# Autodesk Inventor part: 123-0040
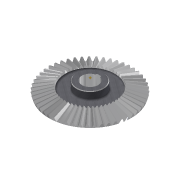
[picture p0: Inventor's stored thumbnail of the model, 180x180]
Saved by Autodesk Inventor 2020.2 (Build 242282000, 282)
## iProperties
+MSCProtocol1+ProtocolID: P00060228092509906
+MSCProtocol2+Protocol: P00060228092509906<@PID>[Version]<@EL>Version=2.2<@EL>[Main]<@EL>VarLists=A,B,C,D,E,F,K<@EL>PartKey=Gears<@EL>Standard=DIN<@EL>View=MODELB<@EL>DataFile=SPIDATA|
Manager: www.cadconsulting.pl
Company: Fabian Stasiak CAD Consulting
Shininess: 20.0
Length Units: 11269
Angle Units: 11279
Time Units: 11290
Mass Units: 11283
Length Display Precision: 3
Angle Display Precision: 2
Created: 2001-01
Part Number: 123-0040
Material: Stal 60
Document SubType Name: Modeling
Description: Koło zęb. stożkowe z=51
Project: Przekładnia X51
Designer: F.Stasiak
Mass: 1037.27 g
Surface Area: 571.297 cm^2
Volume: 132.136 cm^3
Density: 7.85 g/cm^3
Appearance: Chrom
Density: 7.86
Volumn: 5.864026952018771
Area: 31.42094824814569
PropertySet Name: Model Information
Control State: 0
Master: False
Checked Out: False
TAB_mte: 3
TAB_z1: 15
TAB_z2: 51
TAB_betam: 20
TAB_x: 0.1632
TAB_xt: 0
TAB_delta1: 16.3895
TAB_delta2: 73.6105
TAB_IT: 6e26
TAB_fpt1: ±0.01
TAB_fpt2: ±0.011
TAB_tfa: 0
TAB_sk1: 4.305
TAB_sk2: 3.699
TAB_ECs1: -0.03
TAB_ECd1: -0.08
TAB_ECs2: -0.04
TAB_ECd2: -0.1
TAB_hk1: 2.706
TAB_hk2: 1.837
TAB_omega: 90
TAB_de1: 45
TAB_de2: 153
TAB_le: 79.74
TAB_deltaf1: 14.1558
TAB_deltaf2: 70.6745
TAB_alfat: 20
Author: F.Stasiak
Subject: Zbiór ćwiczeń. Autodesk Inventor 2020. Kurs podstawowy
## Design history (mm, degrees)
node "Bryła1"
node "Korpusy bryłowe"
node "Korpusy powierzchniowe"
revolve "Base Body" stored, may be unused: angle "d10" = 360 deg
node "Tooth Plane"
workpoint "Work Point"
sketch "Sketch2"
  geometry: L1 (4.216, 3.832)-(-4.216, 3.832); L2 (0, -6.728)-(4.216, 3.832); L3 (-4.216, 3.832)-(0, -6.728); L4 (0, 2.5)-(0, -3) reference; L5 (0, 2.5)-(0, -3) reference; L6 (0, 2.5)-(0, -3) reference; L7 (0, -73.314)-(0, 27.014) reference; L8 (0, -73.314)-(0, 27.014) reference; L9 (92.65, -15.24)-(-123.534, -15.24) reference; A1 r 6.122 centre (0, -0.607) between (-4.216, 3.832) and (0, -6.728); 1 further point; 1 other entity
  constraints: 6 end point, 3 point on circle, 2 point on line, 1 centre point, 1 horizontal, 1 vertical alignment, 1 other
  dimensions: "d42" = 43.5294 deg angle of L3 L2 (= msp_a2); "d43" = 10.56 distance from line of L2.start L1 (= 1.6 x msp_he); "d54" = 12.54559 distance of L2.start point (0, -19.274) (= msp_y)
extrude "Tooth" cut sketch "Sketch2" distance "d18" = 32.436 (= 1.02 x prf_b); taper "d19" = -1.88111 deg (= msp_a1)
pattern_circular "Tooth Pattern" dims angle "d22" = 360 deg
revolve "Fix Body" stored, may be unused: angle "d23" = 360 deg
sketch "Sketch7"
  geometry: L1 (-28.8, 0)-(38.4, 0) reference; L2 (0, -28.8)-(0, 38.4) reference; 2 further points
  constraints: 1 coincident
hole "Hole" sketch "Sketch7" diameter "d47" = 37.673 (= hole); stored, may be unused: countersink angle "d51" = 60 deg, drill point angle "d53" = 118 deg; dims "d48" = 6, "d49" = 4, "d50" = 2, "d52" = 8
node "Gear Axis"
node "Mesh Plane"
node "Intersection"
sketch "Szkic8"
  geometry: C1 r 25 at (0, 0); A1 r 45.298 centre (0, 0) between (32.114, -31.947) and (32.921, -31.115) reference; A2 r 45.298 centre (0, 0) between (32.921, -31.115) and (35.797, -27.759) reference; A3 r 45.298 centre (0, 0) between (35.797, -27.759) and (36.495, -26.833) reference; A4 r 45.298 centre (0, 0) between (36.495, -26.833) and (38.936, -23.149) reference; A5 r 45.298 centre (0, 0) between (38.936, -23.149) and (39.516, -22.145) reference; A6 r 45.298 centre (0, 0) between (39.516, -22.145) and (41.486, -18.189) reference; A7 r 45.298 centre (0, 0) between (41.486, -18.189) and (41.938, -17.121) reference; A8 r 45.298 centre (0, 0) between (41.938, -17.121) and (43.407, -12.953) reference; A9 r 45.298 centre (0, 0) between (43.407, -12.953) and (43.724, -11.838) reference; A10 r 45.298 centre (0, 0) between (43.724, -11.838) and (44.67, -7.521) reference; A11 r 45.298 centre (0, 0) between (44.67, -7.521) and (44.847, -6.375) reference; A12 r 45.298 centre (0, 0) between (44.847, -6.375) and (45.255, -1.974) reference; A13 r 45.298 centre (0, 0) between (45.255, -1.974) and (45.291, -0.815) reference; A14 r 45.298 centre (0, 0) between (45.291, -0.815) and (45.155, 3.602) reference; A15 r 45.298 centre (0, 0) between (45.155, 3.602) and (45.048, 4.756) reference; A16 r 45.298 centre (0, 0) between (45.048, 4.756) and (44.37, 9.124) reference; A17 r 45.298 centre (0, 0) between (44.37, 9.124) and (44.122, 10.256) reference; A18 r 45.298 centre (0, 0) between (44.122, 10.256) and (42.912, 14.507) reference; A19 r 45.298 centre (0, 0) between (42.912, 14.507) and (42.527, 15.601) reference; A20 r 45.298 centre (0, 0) between (42.527, 15.601) and (40.804, 19.671) reference; A21 r 45.298 centre (0, 0) between (40.804, 19.671) and (40.288, 20.708) reference; A22 r 45.298 centre (0, 0) between (40.288, 20.708) and (38.078, 24.536) reference; A23 r 45.298 centre (0, 0) between (38.078, 24.536) and (37.437, 25.502) reference; A24 r 45.298 centre (0, 0) between (37.437, 25.502) and (34.774, 29.029) reference; A25 r 45.298 centre (0, 0) between (34.774, 29.029) and (34.02, 29.91) reference; A26 r 45.298 centre (0, 0) between (34.02, 29.91) and (30.943, 33.083) reference; A27 r 45.298 centre (0, 0) between (30.943, 33.083) and (30.086, 33.864) reference; A28 r 45.298 centre (0, 0) between (30.086, 33.864) and (26.643, 36.634) reference; A29 r 45.298 centre (0, 0) between (26.643, 36.634) and (25.697, 37.304) reference; A30 r 45.298 centre (0, 0) between (25.697, 37.304) and (21.939, 39.631) reference; A31 r 45.298 centre (0, 0) between (21.939, 39.631) and (20.918, 40.179) reference; A32 r 45.298 centre (0, 0) between (20.918, 40.179) and (16.903, 42.027) reference; A33 r 45.298 centre (0, 0) between (16.903, 42.027) and (15.822, 42.445) reference; A34 r 45.298 centre (0, 0) between (15.822, 42.445) and (11.61, 43.785) reference; A35 r 45.298 centre (0, 0) between (11.61, 43.785) and (10.486, 44.068) reference; A36 r 45.298 centre (0, 0) between (10.486, 44.068) and (6.141, 44.88) reference; A37 r 45.298 centre (0, 0) between (6.141, 44.88) and (4.991, 45.023) reference; A38 r 45.298 centre (0, 0) between (4.991, 45.023) and (0.58, 45.295) reference; A39 r 45.298 centre (0, 0) between (0.58, 45.295) and (-0.58, 45.295) reference; A40 r 45.298 centre (0, 0) between (-0.58, 45.295) and (-4.991, 45.023) reference; A41 r 45.298 centre (0, 0) between (-4.991, 45.023) and (-6.141, 44.88) reference; A42 r 45.298 centre (0, 0) between (-6.141, 44.88) and (-10.486, 44.068) reference; A43 r 45.298 centre (0, 0) between (-10.486, 44.068) and (-11.61, 43.785) reference; A44 r 45.298 centre (0, 0) between (-11.61, 43.785) and (-15.822, 42.445) reference; A45 r 45.298 centre (0, 0) between (-15.822, 42.445) and (-16.903, 42.027) reference; A46 r 45.298 centre (0, 0) between (-16.903, 42.027) and (-20.918, 40.179) reference; A47 r 45.298 centre (0, 0) between (-20.918, 40.179) and (-21.939, 39.631) reference; A48 r 45.298 centre (0, 0) between (-21.939, 39.631) and (-25.697, 37.304) reference; A49 r 45.298 centre (0, 0) between (-25.697, 37.304) and (-26.643, 36.634) reference; A50 r 45.298 centre (0, 0) between (-26.643, 36.634) and (-30.086, 33.864) reference; A51 r 45.298 centre (0, 0) between (-30.086, 33.864) and (-30.943, 33.083) reference; A52 r 45.298 centre (0, 0) between (-30.943, 33.083) and (-34.02, 29.91) reference; A53 r 45.298 centre (0, 0) between (-34.02, 29.91) and (-34.774, 29.029) reference; A54 r 45.298 centre (0, 0) between (-34.774, 29.029) and (-37.437, 25.502) reference; A55 r 45.298 centre (0, 0) between (-37.437, 25.502) and (-38.078, 24.536) reference; A56 r 45.298 centre (0, 0) between (-38.078, 24.536) and (-40.288, 20.708) reference; A57 r 45.298 centre (0, 0) between (-40.288, 20.708) and (-40.804, 19.671) reference; A58 r 45.298 centre (0, 0) between (-40.804, 19.671) and (-42.527, 15.601) reference; A59 r 45.298 centre (0, 0) between (-42.527, 15.601) and (-42.912, 14.507) reference; A60 r 45.298 centre (0, 0) between (-42.912, 14.507) and (-44.122, 10.256) reference; A61 r 45.298 centre (0, 0) between (-44.122, 10.256) and (-44.37, 9.124) reference; A62 r 45.298 centre (0, 0) between (-44.37, 9.124) and (-45.048, 4.756) reference; A63 r 45.298 centre (0, 0) between (-45.048, 4.756) and (-45.155, 3.602) reference; A64 r 45.298 centre (0, 0) between (-45.155, 3.602) and (-45.291, -0.815) reference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
  constraints: 1 centre point, 1 coincident
  dimensions: "d69" = 50 diameter of C1
extrude "Wyciągnięcie proste2" join sketch "Szkic8" distance "d70" = 12; taper "d71" = 0 deg
sketch "Szkic9"
  geometry: C1 r 25 at (0, 0); A1 r 75.346 centre (0, 0) between (65.772, -36.758) and (68.969, -30.335) reference; A2 r 75.346 centre (0, 0) between (68.969, -30.335) and (69.79, -28.397) reference; A3 r 75.346 centre (0, 0) between (69.79, -28.397) and (72.175, -21.63) reference; A4 r 75.346 centre (0, 0) between (72.175, -21.63) and (72.751, -19.605) reference; A5 r 75.346 centre (0, 0) between (72.751, -19.605) and (74.286, -12.597) reference; A6 r 75.346 centre (0, 0) between (74.286, -12.597) and (74.609, -10.516) reference; A7 r 75.346 centre (0, 0) between (74.609, -10.516) and (75.27, -3.372) reference; A8 r 75.346 centre (0, 0) between (75.27, -3.372) and (75.335, -1.268) reference; A9 r 75.346 centre (0, 0) between (75.335, -1.268) and (75.114, 5.903) reference; A10 r 75.346 centre (0, 0) between (75.114, 5.903) and (74.92, 8) reference; A11 r 75.346 centre (0, 0) between (74.92, 8) and (73.82, 15.089) reference; A12 r 75.346 centre (0, 0) between (73.82, 15.089) and (73.369, 17.146) reference; A13 r 75.346 centre (0, 0) between (73.369, 17.146) and (71.406, 24.046) reference; A14 r 75.346 centre (0, 0) between (71.406, 24.046) and (70.706, 26.032) reference; A15 r 75.346 centre (0, 0) between (70.706, 26.032) and (67.91, 32.639) reference; A16 r 75.346 centre (0, 0) between (67.91, 32.639) and (66.971, 34.524) reference; A17 r 75.346 centre (0, 0) between (66.971, 34.524) and (63.384, 40.737) reference; A18 r 75.346 centre (0, 0) between (63.384, 40.737) and (62.221, 42.492) reference; A19 r 75.346 centre (0, 0) between (62.221, 42.492) and (57.897, 48.217) reference; A20 r 75.346 centre (0, 0) between (57.897, 48.217) and (56.528, 49.816) reference; A21 r 75.346 centre (0, 0) between (56.528, 49.816) and (51.533, 54.967) reference; A22 r 75.346 centre (0, 0) between (51.533, 54.967) and (49.977, 56.385) reference; A23 r 75.346 centre (0, 0) between (49.977, 56.385) and (44.388, 60.883) reference; A24 r 75.346 centre (0, 0) between (44.388, 60.883) and (42.67, 62.099) reference; A25 r 75.346 centre (0, 0) between (42.67, 62.099) and (36.57, 65.876) reference; A26 r 75.346 centre (0, 0) between (36.57, 65.876) and (34.715, 66.872) reference; A27 r 75.346 centre (0, 0) between (34.715, 66.872) and (28.197, 69.871) reference; A28 r 75.346 centre (0, 0) between (28.197, 69.871) and (26.234, 70.631) reference; A29 r 75.346 centre (0, 0) between (26.234, 70.631) and (19.397, 72.806) reference; A30 r 75.346 centre (0, 0) between (19.397, 72.806) and (17.355, 73.32) reference; A31 r 75.346 centre (0, 0) between (17.355, 73.32) and (10.303, 74.638) reference; A32 r 75.346 centre (0, 0) between (10.303, 74.638) and (8.214, 74.897) reference; A33 r 75.346 centre (0, 0) between (8.214, 74.897) and (1.053, 75.339) reference; A34 r 75.346 centre (0, 0) between (1.053, 75.339) and (-1.053, 75.339) reference; A35 r 75.346 centre (0, 0) between (-1.053, 75.339) and (-8.214, 74.897) reference; A36 r 75.346 centre (0, 0) between (-8.214, 74.897) and (-10.303, 74.638) reference; A37 r 75.346 centre (0, 0) between (-10.303, 74.638) and (-17.355, 73.32) reference; A38 r 75.346 centre (0, 0) between (-17.355, 73.32) and (-19.397, 72.806) reference; A39 r 75.346 centre (0, 0) between (-19.397, 72.806) and (-26.234, 70.631) reference; A40 r 75.346 centre (0, 0) between (-26.234, 70.631) and (-28.197, 69.871) reference; A41 r 75.346 centre (0, 0) between (-28.197, 69.871) and (-34.715, 66.872) reference; A42 r 75.346 centre (0, 0) between (-34.715, 66.872) and (-36.57, 65.876) reference; A43 r 75.346 centre (0, 0) between (-36.57, 65.876) and (-42.67, 62.099) reference; A44 r 75.346 centre (0, 0) between (-42.67, 62.099) and (-44.388, 60.883) reference; A45 r 75.346 centre (0, 0) between (-44.388, 60.883) and (-49.977, 56.385) reference; A46 r 75.346 centre (0, 0) between (-49.977, 56.385) and (-51.533, 54.967) reference; A47 r 75.346 centre (0, 0) between (-51.533, 54.967) and (-56.528, 49.816) reference; A48 r 75.346 centre (0, 0) between (-56.528, 49.816) and (-57.897, 48.217) reference; A49 r 75.346 centre (0, 0) between (-57.897, 48.217) and (-62.221, 42.492) reference; A50 r 75.346 centre (0, 0) between (-62.221, 42.492) and (-63.384, 40.737) reference; A51 r 75.346 centre (0, 0) between (-63.384, 40.737) and (-66.971, 34.524) reference; A52 r 75.346 centre (0, 0) between (-66.971, 34.524) and (-67.91, 32.639) reference; A53 r 75.346 centre (0, 0) between (-67.91, 32.639) and (-70.706, 26.032) reference; A54 r 75.346 centre (0, 0) between (-70.706, 26.032) and (-71.406, 24.046) reference; A55 r 75.346 centre (0, 0) between (-71.406, 24.046) and (-73.369, 17.146) reference; A56 r 75.346 centre (0, 0) between (-73.369, 17.146) and (-73.82, 15.089) reference; A57 r 75.346 centre (0, 0) between (-73.82, 15.089) and (-74.92, 8) reference; A58 r 75.346 centre (0, 0) between (-74.92, 8) and (-75.114, 5.903) reference; A59 r 75.346 centre (0, 0) between (-75.114, 5.903) and (-75.335, -1.268) reference; A60 r 75.346 centre (0, 0) between (-75.335, -1.268) and (-75.27, -3.372) reference; A61 r 75.346 centre (0, 0) between (-75.27, -3.372) and (-74.609, -10.516) reference; A62 r 75.346 centre (0, 0) between (-74.609, -10.516) and (-74.286, -12.597) reference; A63 r 75.346 centre (0, 0) between (-74.286, -12.597) and (-72.751, -19.605) reference; A64 r 75.346 centre (0, 0) between (-72.751, -19.605) and (-72.175, -21.63) reference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
  constraints: 1 centre point, 1 coincident
  dimensions: "d72" = 50 diameter of C1
extrude "Wyciągnięcie proste3" join sketch "Szkic9" distance "d73" = 12; taper "d74" = 0 deg
revolve "Obrót3" stored, may be unused: angle "d78" = 90 deg
sketch "Szkic11"
  geometry: C1 r 25 at (0, 0) reference
hole "Otwór3" sketch "Szkic11" diameter "d79" = 30; stored, may be unused: countersink angle "d83" = 90 deg, drill point angle "d85" = 118 deg; dims "d80" = 6, "d81" = 4, "d82" = 2, "d84" = 8
fillet "Zaokrąglenie1" dims "d86" = 3
chamfer "Faza1" distance "d87" = 1; stored, may be unused: second distance "d88" = 2, angle "d89" = 45 deg
sketch "Szkic12"
  geometry: L1 (4, 14.457)-(4, 10.9) reference; L2 (-4, 14.457)-(-4, 10.9) reference; L3 (-4, 14.457)-(-4, 16.9); L4 (-4, 16.9)-(4, 16.9); L5 (4, 16.9)-(4, 10.9); L6 (-4, 10.9)-(-4, 14.457); L7 (-4, 10.9)-(4, 10.9); C1 r 24 at (0, 0) reference; 1 further point
  constraints: 10 end point, 2 parallel, 2 perpendicular, 1 collinear, 2 other
  dimensions: "d95" = 6 distance of L4.end L1.end
extrude "Wyciągnięcie proste4" cut sketch "Szkic12" extent not by distance; stored distance "d92" = 12; taper "d93" = 0 deg
sketch "Base Body Sketch"
  geometry: L1 (46.418, 3.807)-(45.298, 0); L2 (46.418, 3.807)-(77.209, -4.205); L3 (77.209, -4.205)-(75.346, -10.537); L4 (-34.121, 0)-(107.571, 0) reference; L5 (45.298, 0)-(0, 0); L6 (0, -10.537)-(75.346, -10.537); L7 (0, 0)-(0, -10.537); L8 (46.418, 3.807)-(0, 15.886); L9 (0, 0)-(0, 15.886); L10 (0, -26.38)-(0, 27.412) reference; L11 (0, 15.886)-(76.5, -6.614); L12 (0, 15.886)-(45.298, 0); L13 (45.298, 0)-(75.346, -10.537)
  constraints: 22 end point, 3 collinear, 2 parallel, 2 perpendicular, 2 point on line
  dimensions: "d33" = 31.8 distance between parallel lines of L3 L1 (= prf_b); "d34" = 154.417 diameter of L2.end L7 (= msp_dae); "d35" = 150.692 diameter of L3.end L7 (= msp_dfe); "d37" = 79.74 distance from line of L3 L8.end (= prf_le); "d41" = 73.6105 deg angle of L9 L11 (= msp_delta); "d59" = 45.29831 distance of L5.end L1.end (derived)
sketch "Sketch3"
  geometry: L1 (-45.298, 0)-(0, 0); L2 (-75.346, -10.537)-(-45.298, 0); L3 (0, -10.537)-(-75.346, -10.537); L4 (0, 0)-(0, -10.537); L5 (-75.346, -10.537)-(75.346, -10.537) reference; L6 (-45.298, 0)-(45.298, 0) reference; L7 (0, -24.791)-(0, 6.761) reference; 1 further point
  constraints: 8 end point, 2 horizontal, 2 point on line, 1 vertical
  dimensions: "d57" = 150.692 diameter of L2.start L7 (= msp_dfe); "d58" = 0 distance between parallel lines of L7 L4; "d60" = 45.29831 distance of L1.start L1.end (= d59)
node "Pętla rzutowana1"
node "Pętla rzutowana2"
sketch "Szkic10"
  geometry: L1 (0, -25.991)-(0, 22.361) reference; L2 (25, -10.537)-(25, -22.537) reference; L3 (25, 0)-(25, 12) reference; L4 (45.298, 0)-(45.889, 2.009) reference; L5 (76.265, -7.413)-(75.346, -10.537) reference; L6 (3.367, 0)-(7.753, 0) reference; L7 (3.367, 0)-(2.21, 0) reference; L8 (-2.21, 0)-(2.21, 0) reference; L9 (-2.21, 0)-(-3.367, 0) reference; L10 (-7.753, 0)-(-3.367, 0) reference; L11 (-7.753, 0)-(-8.893, 0) reference; L12 (-13.179, 0)-(-8.893, 0) reference; L13 (-13.179, 0)-(-14.284, 0) reference; L14 (-18.405, 0)-(-14.284, 0) reference; L15 (-18.405, 0)-(-19.458, 0) reference; L16 (-23.352, 0)-(-19.458, 0) reference; L17 (-23.352, 0)-(-24.337, 0) reference; L18 (-27.945, 0)-(-24.337, 0) reference; L19 (-27.945, 0)-(-28.848, 0) reference; L20 (-32.114, 0)-(-28.848, 0) reference; L21 (-32.114, 0)-(-32.921, 0) reference; L22 (-35.797, 0)-(-32.921, 0) reference; L23 (-35.797, 0)-(-36.495, 0) reference; L24 (-38.936, 0)-(-36.495, 0) reference; L25 (-38.936, 0)-(-39.516, 0) reference; L26 (-41.486, 0)-(-39.516, 0) reference; L27 (-41.486, 0)-(-41.938, 0) reference; L28 (-43.407, 0)-(-41.938, 0) reference; L29 (-43.407, 0)-(-43.724, 0) reference; L30 (-44.67, 0)-(-43.724, 0) reference; L31 (-44.67, 0)-(-44.847, 0) reference; L32 (-45.255, 0)-(-44.847, 0) reference; L33 (-45.255, 0)-(-45.291, 0) reference; L34 (-45.155, 0)-(-45.291, 0) reference; L35 (-45.155, 0)-(-45.048, 0) reference; L36 (-44.37, 0)-(-45.048, 0) reference; L37 (-44.37, 0)-(-44.122, 0) reference; L38 (-42.912, 0)-(-44.122, 0) reference; L39 (-42.912, 0)-(-42.527, 0) reference; L40 (-40.804, 0)-(-42.527, 0) reference; L41 (-40.804, 0)-(-40.288, 0) reference; L42 (-38.078, 0)-(-40.288, 0) reference; L43 (-38.078, 0)-(-37.437, 0) reference; L44 (-34.774, 0)-(-37.437, 0) reference; L45 (-34.774, 0)-(-34.02, 0) reference; L46 (-30.943, 0)-(-34.02, 0) reference; L47 (-30.943, 0)-(-30.086, 0) reference; L48 (-26.643, 0)-(-30.086, 0) reference; L49 (-26.643, 0)-(-25.697, 0) reference; L50 (-21.939, 0)-(-25.697, 0) reference; L51 (-21.939, 0)-(-20.918, 0) reference; L52 (-16.903, 0)-(-20.918, 0) reference; L53 (-16.903, 0)-(-15.822, 0) reference; L54 (-11.61, 0)-(-15.822, 0) reference; L55 (-11.61, 0)-(-10.486, 0) reference; L56 (-6.141, 0)-(-10.486, 0) reference; L57 (-6.141, 0)-(-4.991, 0) reference; L58 (-25, 0)-(25, 0) reference; L59 (-0.58, 0)-(-4.991, 0) reference; L60 (-0.58, 0)-(0.58, 0) reference; L61 (4.991, 0)-(0.58, 0) reference; L62 (4.991, 0)-(6.141, 0) reference; L63 (10.486, 0)-(6.141, 0) reference; L64 (10.486, 0)-(11.61, 0) reference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
  constraints: 16 end point, 5 perpendicular, 3 parallel
  dimensions: "d90" = 3 distance of L86.end L213.end; "d91" = 3 distance of L218.end L127.start
node "Pętla rzutowana3"
node "Pętla rzutowana4"
node "Pętla rzutowana5"
node "Odniesienie1"
node "Odniesienie2"
node "Pętla rzutowana6"
other parameters: "prf_le" = 79.74 [user parameter; used in 3 equation terms], "prf_delta2" = 12.84746 [user parameter; used in 1 equation term], "prf_he2" = 6.6 [user parameter; used in 1 equation term], "prf_dfe2" = 150.692 [user parameter; used in 1 equation term], "prf_dae2" = 154.417 [user parameter; used in 1 equation term], "prf_de2" = 153 [user parameter; used in 1 equation term], "prf_b" = 31.8 [user parameter; used in 2 equation terms], "prf_omega" = 90 deg [user parameter; used in 1 equation term], "msp_delta" = 73.6105 deg (= prf_delta2) [user parameter; used in 3 equation terms], "msp_he" = 6.6 (= prf_he2) [user parameter; used in 2 equation terms], "msp_dfe" = 150.692 (= prf_dfe2) [user parameter; used in 3 equation terms], "msp_dae" = 154.417 (= prf_dae2) [user parameter; used in 2 equation terms], "msp_de" = 153 (= prf_de2) [user parameter; used in 1 equation term], "hole" = 37.673 (= 0.25 x msp_dfe) [user parameter; used in 1 equation term], "msp_y" = 12.54559 (computed from msp_delta, msp_dae, msp_he) [user parameter; used in 1 equation term], "msp_a1" = -1.88111 deg (computed from msp_de, msp_z, prf_le) [user parameter; used in 1 equation term], "msp_a2" = 43.5294 deg (computed from msp_z) [user parameter; used in 1 equation term], "msp_dist" = 22.49989 (computed from prf_le, msp_delta) [user parameter], "d0" = 3.62545 (derived), "d4" = 38.7702 (derived), "d6" = 32.175 (derived), "d8" = 21.89 (derived), "d12" = 0 (derived), "d14" = -13.24579 (derived), "d16" = 9.83731 (derived), "d40" = 19.14 (derived), "d61" = 90 deg, "d64" = 0, "d65" = 90 deg (= prf_omega), "d66" = 2.94118 (computed from prf_z1, prf_z2), "d67" = 0, "d68" = 0
